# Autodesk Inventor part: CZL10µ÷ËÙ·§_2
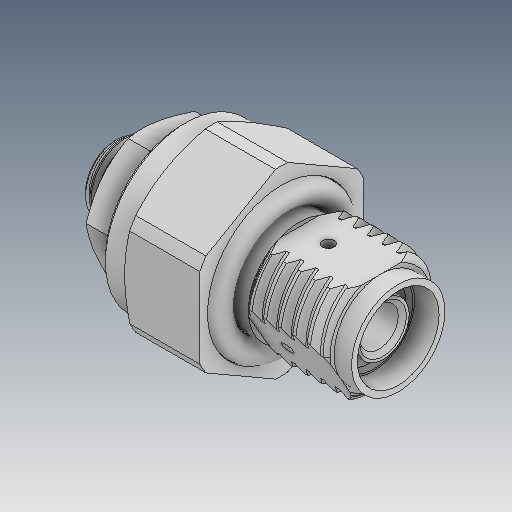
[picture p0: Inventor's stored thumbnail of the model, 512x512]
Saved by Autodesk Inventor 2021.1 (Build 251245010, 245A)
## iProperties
Created: 2019-04
Part Number: CZL10µ÷ËÙ·§_2
Material: Ogólny
Document SubType Name: Modeling
Designer: user
Density: 1 g/cm^3
Appearance: Domyślna
Author: user
Revision Number: ÈÎºÎ
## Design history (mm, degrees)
feature "ÊäÈë1"
feature "ÊäÈë2"
feature "ÊäÈë3"
node "Bryła1"
node "Bryła2"
node "Bryła3"
